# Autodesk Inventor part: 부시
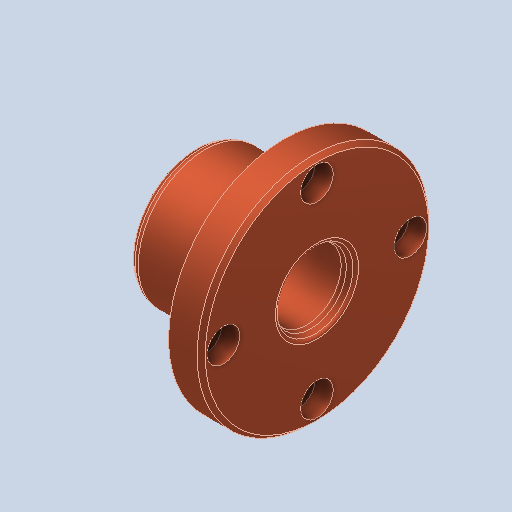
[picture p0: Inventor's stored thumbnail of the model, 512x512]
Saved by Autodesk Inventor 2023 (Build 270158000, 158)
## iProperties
Created: 2024-09
Part Number: 부시
Material: 구리, 합금
Document SubType Name: Modeling
Designer: home
Density: 8.92 g/cm^3
Appearance: 기본값
Author: jhkim
Sending System: Autodesk Inventor 2025
Preprocessor: ST-DEVELOPER v20
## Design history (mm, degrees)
feature "솔리드1"
node "솔리드2"
